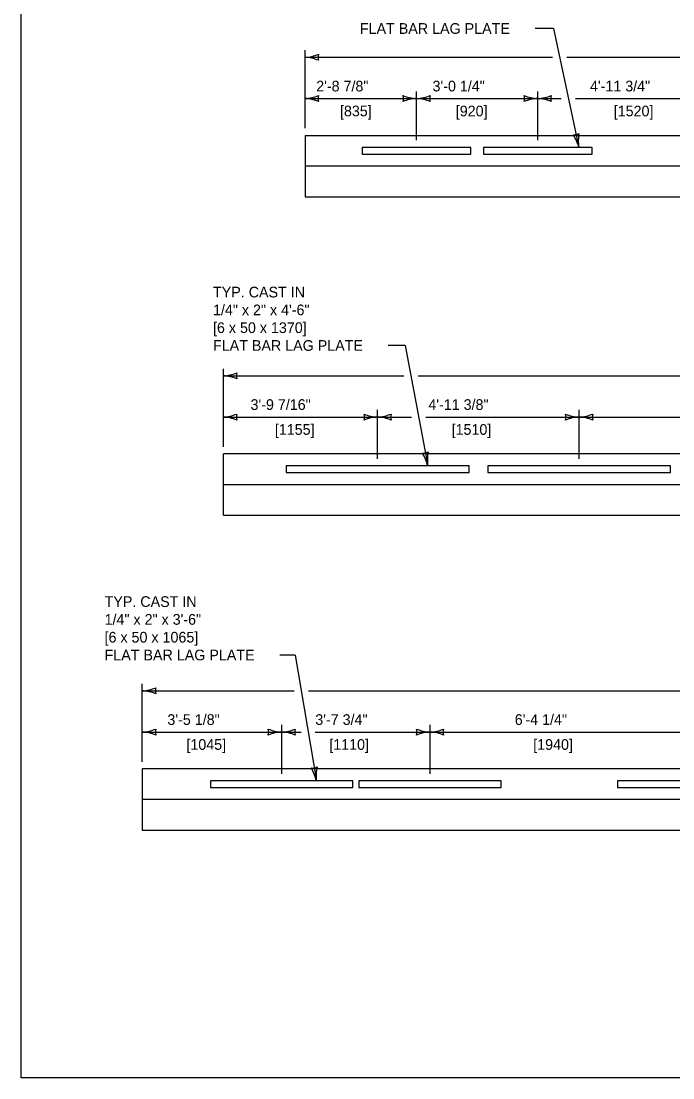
# Model space of a CAD drawing. Extents: x 49991.4 to 50021, y 49987.6 to 50011.4.
# Drawn here: x 49999.38 to 50003.05, y 49987.8 to 49993.74 of the extents above; entities that cross this region are included whole.
import ezdxf

# ---------------------------------------------------------------- set-up
doc = ezdxf.new("R2010")
doc.units = 0
for name, color, linetype in [('Level 1', 7, 'Continuous'), ('Level 2', 7, 'Continuous'), ('Level 3', 7, 'Continuous'), ('Level 5', 7, 'Continuous')]:
    doc.layers.add(name, color=color, linetype=linetype)

msp = doc.modelspace()

# ---------------------------------------------------------------- linework, layer by layer
at = {"layer": 'Level 1'}
for p, q in [((50000.9788, 49993.0937), (50000.9788, 49992.7487)), ((50000.9788, 49993.0937), (50008.4087, 49993.0937)), ((50001.9098, 49993.0265), (50001.3002, 49993.0265)), ((50001.3002, 49993.0265), (50001.3002, 49992.9884)), ((50001.9098, 49992.9884), (50001.9098, 49993.0265)), ((50002.5911, 49993.0265), (50001.9815, 49993.0265)), ((50001.9815, 49993.0265), (50001.9815, 49992.9884)), ((50002.5911, 49992.9884), (50002.5911, 49993.0265)), ((50001.3002, 49992.9884), (50001.9098, 49992.9884)), ((50001.9815, 49992.9884), (50002.5911, 49992.9884)), ((50008.4087, 49992.9212), (50000.9788, 49992.9212)), ((50000.9788, 49992.7487), (50008.4087, 49992.7487)), ((50008.8676, 49991.3045), (50000.5199, 49991.3045)), ((50000.5199, 49991.132), (50000.5199, 49991.3045)), ((50001.8999, 49991.2373), (50000.8724, 49991.2373)), ((50000.8724, 49991.2373), (50000.8724, 49991.1991)), ((50001.8999, 49991.1991), (50001.8999, 49991.2373)), ((50003.0324, 49991.2373), (50002.0049, 49991.2373)), ((50002.0049, 49991.2373), (50002.0049, 49991.1991)), ((50003.0324, 49991.1991), (50003.0324, 49991.2373)), ((50000.8724, 49991.1991), (50001.8999, 49991.1991)), ((50002.0049, 49991.1991), (50003.0324, 49991.1991)), ((50000.5199, 49990.9594), (50000.5199, 49991.132)), ((50000.5199, 49991.132), (50008.8676, 49991.132)), ((50000.5199, 49990.9594), (50008.8676, 49990.9594)), ((50000.0644, 49989.5348), (50000.0644, 49989.1898)), ((50009.3231, 49989.5348), (50000.0644, 49989.5348)), ((50001.2479, 49989.4677), (50000.4477, 49989.4677)), ((50000.4477, 49989.4677), (50000.4477, 49989.4295)), ((50001.2479, 49989.4295), (50001.2479, 49989.4677)), ((50002.0813, 49989.4677), (50001.2812, 49989.4677)), ((50001.2812, 49989.4677), (50001.2812, 49989.4295)), ((50002.0813, 49989.4295), (50002.0813, 49989.4677)), ((50003.5341, 49989.4677), (50002.734, 49989.4677)), ((50002.734, 49989.4677), (50002.734, 49989.4295)), ((50000.4477, 49989.4295), (50001.2479, 49989.4295)), ((50001.2812, 49989.4295), (50002.0813, 49989.4295)), ((50002.734, 49989.4295), (50003.5341, 49989.4295)), ((50009.3231, 49989.3623), (50000.0644, 49989.3623)), ((50000.0644, 49989.1898), (50009.3231, 49989.1898))]:
    msp.add_line(p, q, dxfattribs=at)
msp.add_lwpolyline([(49999.3835, 49998.9992), (50016.7501, 49998.9992), (50016.7501, 49987.7988), (49999.3835, 49987.7988)], close=True, dxfattribs=at)
at = {"layer": 'Level 3'}
for p, q in [((50002.3744, 49993.6941), (50002.2718, 49993.6941)), ((50002.3744, 49993.6941), (50002.517, 49993.0265)), ((50000.9788, 49993.1337), (50000.9788, 49993.5722)), ((50000.9788, 49993.5322), (50002.369, 49993.5322)), ((50002.449, 49993.5322), (50008.4087, 49993.5322)), ((50000.9788, 49993.3006), (50001.605, 49993.3006)), ((50001.605, 49993.3006), (50002.2863, 49993.3006)), ((50002.2863, 49993.3006), (50002.4184, 49993.3006)), ((50002.4984, 49993.3006), (50003.4335, 49993.3006)), ((50001.5418, 49991.9133), (50001.4465, 49991.9133)), ((50001.5418, 49991.9133), (50001.6681, 49991.2373)), ((50000.5199, 49991.3445), (50000.5199, 49991.7829)), ((50000.5199, 49991.7429), (50001.5337, 49991.7429)), ((50001.6137, 49991.7429), (50008.8676, 49991.7429)), ((50000.5199, 49991.5114), (50001.3861, 49991.5114)), ((50001.3861, 49991.5114), (50001.5769, 49991.5114)), ((50001.6569, 49991.5114), (50002.5187, 49991.5114)), ((50002.5187, 49991.5114), (50004.1275, 49991.5114)), ((50000.9236, 49990.1744), (50000.8374, 49990.1744)), ((50000.9236, 49990.1744), (50001.0422, 49989.4677)), ((50000.0644, 49989.5748), (50000.0644, 49990.0133)), ((50000.0644, 49989.9733), (50000.9174, 49989.9733)), ((50000.9974, 49989.9733), (50009.3231, 49989.9733)), ((50000.0644, 49989.7417), (50000.8478, 49989.7417)), ((50000.8478, 49989.7417), (50000.9562, 49989.7417)), ((50001.0362, 49989.7417), (50001.6812, 49989.7417)), ((50001.6812, 49989.7417), (50003.1341, 49989.7417))]:
    msp.add_line(p, q, dxfattribs=at)
for centre, radius, start, end in [((50000.9673, 49993.7649), 0.233, 272.82731, 292.07716), ((50001.107, 49993.5322), 0.0548, 162.13882, 197.86118), ((50000.9696, 49993.3101), 0.2223, 67.45601, 87.63952), ((50000.9673, 49993.5334), 0.233, 272.82059, 292.07044), ((50001.107, 49993.3006), 0.0548, 162.1321, 197.85446), ((50001.4768, 49993.3006), 0.0548, 342.1321, 17.85446), ((50001.6142, 49993.5227), 0.2223, 247.44929, 267.6328), ((50001.5935, 49993.5333), 0.233, 272.82731, 292.07716), ((50001.7332, 49993.3006), 0.0548, 162.13882, 197.86118), ((50002.2954, 49993.5227), 0.2223, 247.45601, 267.63952), ((50002.158, 49993.3006), 0.0548, 342.13882, 17.86118), ((50002.2748, 49993.5333), 0.233, 272.82731, 292.07716), ((50002.4145, 49993.3006), 0.0548, 162.13882, 197.86118), ((50000.9696, 49993.0785), 0.2223, 67.44929, 87.6328), ((50001.6165, 49993.0679), 0.233, 92.82059, 112.07044), ((50001.5959, 49993.0784), 0.2223, 67.45601, 87.63952), ((50002.2978, 49993.0679), 0.233, 92.82731, 112.07716), ((50002.2771, 49993.0784), 0.2223, 67.45601, 87.63952), ((50002.4902, 49993.1519), 0.0548, 264.19144, 299.91381), ((50002.2918, 49992.9667), 0.233, 14.87994, 34.12979), ((50002.7361, 49993.064), 0.2223, 169.50864, 189.69214), ((50000.5084, 49991.9756), 0.233, 272.82731, 292.07716), ((50000.5107, 49991.5208), 0.2223, 67.45601, 87.63952), ((50000.6481, 49991.7429), 0.0548, 162.13882, 197.86118), ((50000.5084, 49991.7441), 0.233, 272.82731, 292.07716), ((50000.5107, 49991.2892), 0.2223, 67.45601, 87.63952), ((50000.6481, 49991.5114), 0.0548, 162.13882, 197.86118), ((50001.3953, 49991.7335), 0.2223, 247.45601, 267.63952), ((50001.2579, 49991.5114), 0.0548, 342.13882, 17.86118), ((50001.3976, 49991.2786), 0.233, 92.82731, 112.07716), ((50001.3747, 49991.7441), 0.233, 272.82731, 292.07716), ((50001.377, 49991.2892), 0.2223, 67.45601, 87.63952), ((50001.5144, 49991.5114), 0.0548, 162.13882, 197.86118), ((50002.5278, 49991.7335), 0.2223, 247.45601, 267.63952), ((50002.3905, 49991.5114), 0.0548, 342.13882, 17.86118), ((50002.5302, 49991.2786), 0.233, 92.82731, 112.07716), ((50002.5072, 49991.7441), 0.233, 272.82731, 292.07716), ((50002.5095, 49991.2892), 0.2223, 67.45601, 87.63952), ((50002.6469, 49991.5114), 0.0548, 162.13882, 197.86118), ((50001.6446, 49991.3634), 0.0548, 262.72124, 298.4436), ((50001.4415, 49991.1833), 0.233, 13.40973, 32.65958), ((50001.8881, 49991.2691), 0.2223, 168.03843, 188.22194), ((50000.0529, 49990.206), 0.233, 272.82731, 292.07716), ((50000.1926, 49989.9733), 0.0548, 162.13882, 197.86118), ((50000.0552, 49989.7512), 0.2223, 67.45601, 87.63952), ((50000.0529, 49989.9744), 0.233, 272.82731, 292.07716), ((50000.1926, 49989.7417), 0.0548, 162.13882, 197.86118), ((50000.857, 49989.9639), 0.2223, 247.45601, 267.63952), ((50000.7196, 49989.7417), 0.0548, 342.13882, 17.86118), ((50000.8363, 49989.9744), 0.233, 272.82731, 292.07716), ((50000.976, 49989.7417), 0.0548, 162.13882, 197.86118), ((50001.6904, 49989.9639), 0.2223, 247.45601, 267.63952), ((50001.553, 49989.7417), 0.0548, 342.13882, 17.86118), ((50001.6697, 49989.9744), 0.233, 272.82731, 292.07716), ((50001.8094, 49989.7417), 0.0548, 162.13882, 197.86118), ((50000.0552, 49989.5196), 0.2223, 67.45601, 87.63952), ((50000.8593, 49989.509), 0.233, 92.82731, 112.07716), ((50000.8386, 49989.5196), 0.2223, 67.45601, 87.63952), ((50001.6927, 49989.509), 0.233, 92.82731, 112.07716), ((50001.6721, 49989.5196), 0.2223, 67.45601, 87.63952), ((50001.021, 49989.5942), 0.0548, 261.66353, 297.38589), ((50000.8146, 49989.4179), 0.233, 12.35202, 31.60187), ((50001.2628, 49989.4954), 0.2223, 166.98072, 187.16423)]:
    msp.add_arc(centre, radius, start, end, dxfattribs=at)
at = {"layer": 'Level 5'}
for p, q in [((50001.605, 49993.0665), (50001.605, 49993.3406)), ((50002.2863, 49993.0665), (50002.2863, 49993.3406)), ((50001.3861, 49991.2773), (50001.3861, 49991.5514)), ((50002.5187, 49991.2773), (50002.5187, 49991.5514)), ((50000.8478, 49989.5077), (50000.8478, 49989.7817)), ((50001.6812, 49989.5077), (50001.6812, 49989.7817))]:
    msp.add_line(p, q, dxfattribs=at)

# ---------------------------------------------------------------- texts
at = {"layer": 'Level 2'}
for s, p in [('FLAT BAR LAG PLATE', (50001.2868, 49993.6641)), ('2\'-8 7/8"', (50001.0413, 49993.3406)), ('3\'-0 1/4"', (50001.695, 49993.3406)), ('4\'-11 3/4"', (50002.5795, 49993.3406)), ('[835]', (50001.1748, 49993.2006)), ('[920]', (50001.8255, 49993.2006)), ('[1520]', (50002.7129, 49993.2006)), ('TYP. CAST IN', (50000.4615, 49992.1833)), ('1/4" x 2" x 4\'-6"', (50000.4615, 49992.0833)), ('[6 x 50 x 1370]', (50000.4615, 49991.9833)), ('FLAT BAR LAG PLATE', (50000.4615, 49991.8833)), ('3\'-9 7/16"', (50000.6724, 49991.5514)), ('4\'-11 3/8"', (50001.6714, 49991.5514)), ('[1155]', (50000.8089, 49991.4114)), ('[1510]', (50001.8022, 49991.4114)), ('TYP. CAST IN', (49999.8524, 49990.4444)), ('1/4" x 2" x 3\'-6"', (49999.8524, 49990.3444)), ('[6 x 50 x 1065]', (49999.8524, 49990.2444)), ('FLAT BAR LAG PLATE', (49999.8524, 49990.1444)), ('3\'-5 1/8"', (50000.2055, 49989.7817)), ('3\'-7 3/4"', (50001.0362, 49989.7817)), ('6\'-4 1/4"', (50002.157, 49989.7817)), ('[1045]', (50000.312, 49989.6417)), ('[1110]', (50001.1149, 49989.6417)), ('[1940]', (50002.2606, 49989.6417))]:
    msp.add_text(s, height=0.06, dxfattribs=at).set_placement(p)

doc.saveas('drawing.dxf')
